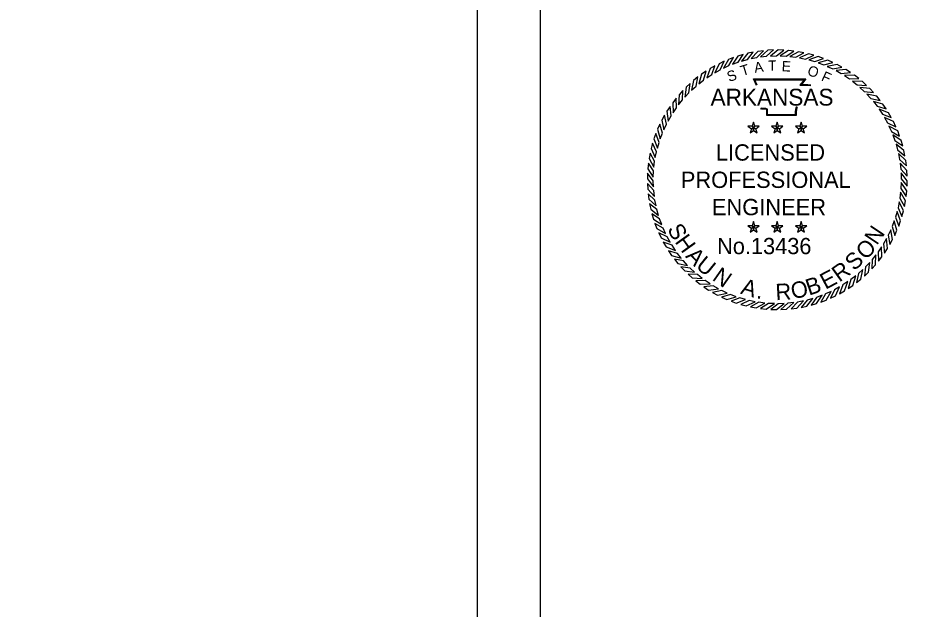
# Model space of a CAD drawing. Extents: x 759422 to 1448857, y 1662254 to 2059437.
# Drawn here: x 1448448.5 to 1448856.9, y 2058891.6 to 2059163.3 of the extents above; entities that cross this region are included whole.
import ezdxf

# ---------------------------------------------------------------- set-up
doc = ezdxf.new("R2010")
doc.units = 0
doc.layers.add('1', color=7, linetype='Continuous')
doc.layers.add('G-ANNO-SYMB', color=7, linetype='Continuous')

msp = doc.modelspace()

# ---------------------------------------------------------------- linework, layer by layer
at = {"layer": '1'}
msp.add_line((1448659.58, 2058365.37), (1448659.58, 2059407.69), dxfattribs=at)
msp.add_lwpolyline([(1448688.42, 2059436.53), (1446988.42, 2059436.53), (1446988.42, 2058336.53), (1448688.42, 2058336.53)], close=True, dxfattribs=at)
at = {"layer": 'G-ANNO-SYMB'}
for points in [[(1448781.61, 2059146.49), (1448779.15, 2059145.77), (1448776.6, 2059141.98), (1448779.2, 2059142.92)], [(1448786.18, 2059147.54), (1448783.67, 2059147.01), (1448780.82, 2059143.43), (1448783.5, 2059144.16)], [(1448790.82, 2059148.22), (1448788.27, 2059147.89), (1448785.15, 2059144.55), (1448787.87, 2059145.07)], [(1448795.49, 2059148.54), (1448792.93, 2059148.41), (1448789.56, 2059145.32), (1448792.31, 2059145.63)], [(1448800.17, 2059148.49), (1448797.61, 2059148.56), (1448794.01, 2059145.75), (1448796.78, 2059145.83)], [(1448804.84, 2059148.07), (1448802.29, 2059148.34), (1448798.48, 2059145.82), (1448801.24, 2059145.69)], [(1448809.46, 2059147.29), (1448806.94, 2059147.76), (1448802.94, 2059145.54), (1448805.69, 2059145.2)], [(1448814, 2059146.15), (1448811.52, 2059146.82), (1448807.36, 2059144.92), (1448810.08, 2059144.36)], [(1448818.44, 2059144.65), (1448816.02, 2059145.51), (1448811.73, 2059143.95), (1448814.39, 2059143.18)], [(1448768.6, 2059141.26), (1448766.38, 2059139.99), (1448764.78, 2059135.7), (1448767.09, 2059137.23)], [(1448772.8, 2059143.35), (1448770.48, 2059142.25), (1448768.55, 2059138.1), (1448770.98, 2059139.44)], [(1448777.14, 2059145.09), (1448774.75, 2059144.18), (1448772.5, 2059140.2), (1448775.02, 2059141.34)], [(1448822.75, 2059142.81), (1448820.41, 2059143.86), (1448816, 2059142.64), (1448818.59, 2059141.66)], [(1448826.9, 2059140.64), (1448824.65, 2059141.87), (1448820.16, 2059141), (1448822.67, 2059139.82)], [(1448764.58, 2059138.86), (1448762.46, 2059137.41), (1448761.2, 2059133.02), (1448763.39, 2059134.71)], [(1448830.87, 2059138.15), (1448828.72, 2059139.55), (1448824.18, 2059139.04), (1448826.58, 2059137.66)], [(1448757.17, 2059133.14), (1448755.3, 2059131.38), (1448754.75, 2059126.84), (1448756.64, 2059128.86)], [(1448760.76, 2059136.15), (1448758.76, 2059134.54), (1448757.85, 2059130.06), (1448759.9, 2059131.92)], [(1448834.63, 2059135.36), (1448832.6, 2059136.92), (1448828.03, 2059136.76), (1448830.32, 2059135.21)], [(1448838.16, 2059132.28), (1448836.25, 2059134), (1448831.69, 2059134.2), (1448833.85, 2059132.47)], [(1448753.82, 2059129.87), (1448752.1, 2059127.96), (1448751.9, 2059123.39), (1448753.63, 2059125.56)], [(1448841.43, 2059128.93), (1448839.67, 2059130.79), (1448835.13, 2059131.35), (1448837.15, 2059129.45)], [(1448750.74, 2059126.34), (1448749.17, 2059124.3), (1448749.33, 2059119.73), (1448750.89, 2059122.03)], [(1448844.44, 2059125.34), (1448842.83, 2059127.33), (1448838.35, 2059128.24), (1448840.21, 2059126.19)], [(1448847.15, 2059121.52), (1448845.7, 2059123.63), (1448841.31, 2059124.89), (1448843.01, 2059122.7)], [(1448747.95, 2059122.58), (1448746.54, 2059120.43), (1448747.06, 2059115.88), (1448748.43, 2059118.29)], [(1448849.56, 2059117.5), (1448848.28, 2059119.72), (1448843.99, 2059121.32), (1448845.52, 2059119.01)], [(1448745.46, 2059118.61), (1448744.23, 2059116.36), (1448745.1, 2059111.87), (1448746.28, 2059114.38)], [(1448851.64, 2059113.3), (1448850.54, 2059115.62), (1448846.39, 2059117.55), (1448847.73, 2059115.12)], [(1448743.28, 2059114.46), (1448742.24, 2059112.12), (1448743.46, 2059107.71), (1448744.44, 2059110.3)], [(1448786.28, 2059112.66), (1448785.67, 2059113.5), (1448783.69, 2059113.5), (1448785.29, 2059112.34)], [(1448786.28, 2059112.66), (1448785.29, 2059112.34), (1448784.68, 2059110.45), (1448786.28, 2059111.62)], [(1448786.28, 2059112.66), (1448786.9, 2059113.5), (1448786.28, 2059115.39), (1448785.67, 2059113.5)], [(1448786.28, 2059112.66), (1448787.28, 2059112.34), (1448788.88, 2059113.5), (1448786.9, 2059113.5)], [(1448786.28, 2059112.66), (1448786.28, 2059111.62), (1448787.89, 2059110.45), (1448787.28, 2059112.34)], [(1448797.19, 2059112.66), (1448796.58, 2059113.5), (1448794.6, 2059113.5), (1448796.2, 2059112.34)], [(1448797.19, 2059112.66), (1448796.2, 2059112.34), (1448795.59, 2059110.45), (1448797.19, 2059111.62)], [(1448797.19, 2059112.66), (1448797.81, 2059113.5), (1448797.19, 2059115.39), (1448796.58, 2059113.5)], [(1448797.19, 2059112.66), (1448798.18, 2059112.34), (1448799.79, 2059113.5), (1448797.81, 2059113.5)], [(1448797.19, 2059112.66), (1448797.19, 2059111.62), (1448798.8, 2059110.45), (1448798.18, 2059112.34)], [(1448808.1, 2059112.66), (1448807.49, 2059113.5), (1448805.51, 2059113.5), (1448807.11, 2059112.34)], [(1448808.1, 2059112.66), (1448807.11, 2059112.34), (1448806.5, 2059110.45), (1448808.1, 2059111.62)], [(1448808.1, 2059112.66), (1448808.72, 2059113.5), (1448808.1, 2059115.39), (1448807.49, 2059113.5)], [(1448808.1, 2059112.66), (1448809.09, 2059112.34), (1448810.7, 2059113.5), (1448808.72, 2059113.5)], [(1448808.1, 2059112.66), (1448808.1, 2059111.62), (1448809.71, 2059110.45), (1448809.09, 2059112.34)], [(1448853.38, 2059108.95), (1448852.47, 2059111.35), (1448848.49, 2059113.6), (1448849.63, 2059111.08)], [(1448741.45, 2059110.15), (1448740.58, 2059107.73), (1448742.15, 2059103.44), (1448742.92, 2059106.1)], [(1448854.78, 2059104.48), (1448854.06, 2059106.94), (1448850.27, 2059109.5), (1448851.21, 2059106.89)], [(1448739.95, 2059105.71), (1448739.28, 2059103.23), (1448741.18, 2059099.07), (1448741.74, 2059101.79)], [(1448855.83, 2059099.92), (1448855.3, 2059102.43), (1448851.72, 2059105.27), (1448852.45, 2059102.6)], [(1448738.81, 2059101.17), (1448738.34, 2059098.65), (1448740.55, 2059094.65), (1448740.9, 2059097.4)], [(1448856.51, 2059095.28), (1448856.18, 2059097.83), (1448852.84, 2059100.94), (1448853.36, 2059098.22)], [(1448738.03, 2059096.55), (1448737.75, 2059094), (1448740.28, 2059090.18), (1448740.41, 2059092.95)], [(1448856.83, 2059090.61), (1448856.7, 2059093.17), (1448853.61, 2059096.54), (1448853.92, 2059093.79)], [(1448737.61, 2059091.88), (1448737.54, 2059089.32), (1448740.35, 2059085.71), (1448740.26, 2059088.48)], [(1448856.78, 2059085.92), (1448856.85, 2059088.49), (1448854.04, 2059092.09), (1448854.12, 2059089.32)], [(1448737.56, 2059087.2), (1448737.69, 2059084.64), (1448740.78, 2059081.26), (1448740.47, 2059084.02)], [(1448856.36, 2059081.26), (1448856.64, 2059083.81), (1448854.11, 2059087.62), (1448853.98, 2059084.85)], [(1448737.88, 2059082.52), (1448738.21, 2059079.98), (1448741.55, 2059076.86), (1448741.03, 2059079.58)], [(1448855.58, 2059076.64), (1448856.05, 2059079.16), (1448853.84, 2059083.16), (1448853.49, 2059080.41)], [(1448738.56, 2059077.89), (1448739.09, 2059075.38), (1448742.67, 2059072.53), (1448741.93, 2059075.21)], [(1448854.44, 2059072.1), (1448855.11, 2059074.57), (1448853.21, 2059078.73), (1448852.65, 2059076.02)], [(1448739.6, 2059073.32), (1448740.33, 2059070.86), (1448744.12, 2059068.31), (1448743.18, 2059070.91)], [(1448852.94, 2059067.66), (1448853.8, 2059070.07), (1448852.24, 2059074.37), (1448851.47, 2059071.71)], [(1448741, 2059068.85), (1448741.92, 2059066.46), (1448745.9, 2059064.2), (1448744.76, 2059066.73)], [(1448786.28, 2059066.98), (1448785.67, 2059067.82), (1448783.69, 2059067.82), (1448785.29, 2059066.66)], [(1448786.28, 2059066.98), (1448786.9, 2059067.82), (1448786.28, 2059069.7), (1448785.67, 2059067.82)], [(1448786.28, 2059066.98), (1448787.28, 2059066.66), (1448788.88, 2059067.82), (1448786.9, 2059067.82)], [(1448797.19, 2059066.98), (1448796.58, 2059067.82), (1448794.6, 2059067.82), (1448796.2, 2059066.66)], [(1448797.19, 2059066.98), (1448797.81, 2059067.82), (1448797.19, 2059069.7), (1448796.58, 2059067.82)], [(1448797.19, 2059066.98), (1448798.18, 2059066.66), (1448799.79, 2059067.82), (1448797.81, 2059067.82)], [(1448808.1, 2059066.98), (1448807.49, 2059067.82), (1448805.51, 2059067.82), (1448807.11, 2059066.66)], [(1448808.1, 2059066.98), (1448808.72, 2059067.82), (1448808.1, 2059069.7), (1448807.49, 2059067.82)], [(1448808.1, 2059066.98), (1448809.09, 2059066.66), (1448810.7, 2059067.82), (1448808.72, 2059067.82)], [(1448851.1, 2059063.35), (1448852.15, 2059065.69), (1448850.93, 2059070.1), (1448849.95, 2059067.5)], [(1448742.75, 2059064.51), (1448743.85, 2059062.19), (1448747.99, 2059060.26), (1448746.66, 2059062.68)], [(1448786.28, 2059066.98), (1448785.29, 2059066.66), (1448784.68, 2059064.77), (1448786.28, 2059065.94)], [(1448786.28, 2059066.98), (1448786.28, 2059065.94), (1448787.89, 2059064.77), (1448787.28, 2059066.66)], [(1448797.19, 2059066.98), (1448796.2, 2059066.66), (1448795.59, 2059064.77), (1448797.19, 2059065.94)], [(1448797.19, 2059066.98), (1448797.19, 2059065.94), (1448798.8, 2059064.77), (1448798.18, 2059066.66)], [(1448808.1, 2059066.98), (1448807.11, 2059066.66), (1448806.5, 2059064.77), (1448808.1, 2059065.94)], [(1448808.1, 2059066.98), (1448808.1, 2059065.94), (1448809.71, 2059064.77), (1448809.09, 2059066.66)], [(1448848.93, 2059059.2), (1448850.16, 2059061.45), (1448849.29, 2059065.94), (1448848.11, 2059063.43)], [(1448744.83, 2059060.31), (1448746.11, 2059058.09), (1448750.39, 2059056.48), (1448748.87, 2059058.8)], [(1448846.44, 2059055.23), (1448847.84, 2059057.38), (1448847.33, 2059061.92), (1448845.95, 2059059.51)], [(1448747.24, 2059056.29), (1448748.69, 2059054.17), (1448753.08, 2059052.91), (1448751.38, 2059055.1)], [(1448843.65, 2059051.47), (1448845.21, 2059053.5), (1448845.06, 2059058.07), (1448843.5, 2059055.78)], [(1448749.95, 2059052.47), (1448751.56, 2059050.47), (1448756.04, 2059049.56), (1448754.18, 2059051.61)], [(1448840.57, 2059047.94), (1448842.29, 2059049.84), (1448842.49, 2059054.41), (1448840.76, 2059052.25)], [(1448752.95, 2059048.88), (1448754.72, 2059047.01), (1448759.25, 2059046.45), (1448757.23, 2059048.35)], [(1448833.63, 2059041.66), (1448835.62, 2059043.27), (1448836.54, 2059047.75), (1448834.49, 2059045.88)], [(1448837.22, 2059044.66), (1448839.09, 2059046.43), (1448839.64, 2059050.96), (1448837.75, 2059048.94)], [(1448756.23, 2059045.53), (1448758.13, 2059043.81), (1448762.7, 2059043.61), (1448760.54, 2059045.34)], [(1448829.81, 2059038.95), (1448831.92, 2059040.4), (1448833.19, 2059044.79), (1448831, 2059043.09)], [(1448759.76, 2059042.45), (1448761.79, 2059040.88), (1448766.36, 2059041.04), (1448764.07, 2059042.6)], [(1448763.52, 2059039.66), (1448765.67, 2059038.25), (1448770.21, 2059038.77), (1448767.8, 2059040.14)], [(1448821.59, 2059034.46), (1448823.91, 2059035.56), (1448825.84, 2059039.7), (1448823.41, 2059038.37)], [(1448825.79, 2059036.54), (1448828.01, 2059037.82), (1448829.61, 2059042.1), (1448827.3, 2059040.58)], [(1448767.49, 2059037.16), (1448769.74, 2059035.94), (1448774.23, 2059036.81), (1448771.72, 2059037.99)], [(1448771.64, 2059034.99), (1448773.98, 2059033.94), (1448778.39, 2059035.17), (1448775.79, 2059036.15)], [(1448812.77, 2059031.31), (1448815.24, 2059032.04), (1448817.79, 2059035.83), (1448815.18, 2059034.89)], [(1448817.24, 2059032.71), (1448819.64, 2059033.63), (1448821.89, 2059037.61), (1448819.37, 2059036.47)], [(1448775.95, 2059033.15), (1448778.36, 2059032.29), (1448782.66, 2059033.86), (1448780, 2059034.63)], [(1448780.39, 2059031.66), (1448782.86, 2059030.99), (1448787.03, 2059032.89), (1448784.31, 2059033.45)], [(1448784.93, 2059030.52), (1448787.45, 2059030.04), (1448791.45, 2059032.26), (1448788.7, 2059032.61)], [(1448789.55, 2059029.74), (1448792.1, 2059029.46), (1448795.91, 2059031.99), (1448793.14, 2059032.12)], [(1448794.22, 2059029.32), (1448796.78, 2059029.25), (1448800.38, 2059032.06), (1448797.61, 2059031.97)], [(1448798.9, 2059029.27), (1448801.46, 2059029.4), (1448804.83, 2059032.49), (1448802.08, 2059032.18)], [(1448803.57, 2059029.59), (1448806.12, 2059029.91), (1448809.24, 2059033.26), (1448806.51, 2059032.74)], [(1448808.21, 2059030.27), (1448810.72, 2059030.8), (1448813.56, 2059034.38), (1448810.89, 2059033.64)]]:
    msp.add_lwpolyline(points, close=True, dxfattribs=at)
for points in [[(1448787.64, 2059132.2), (1448786.25, 2059135.21), (1448810.31, 2059135.23), (1448808.3, 2059132.7), (1448809.93, 2059132.72), (1448811.3, 2059132.74), (1448812.66, 2059132.59)], [(1448787.98, 2059132.36), (1448786.84, 2059134.83), (1448809.52, 2059134.85), (1448807.5, 2059132.31), (1448809.94, 2059132.34), (1448811.28, 2059132.36), (1448812.62, 2059132.21)], [(1448806.52, 2059122.12), (1448806.11, 2059121.78), (1448805.97, 2059121.29), (1448805.83, 2059120.04), (1448805.83, 2059118.37), (1448792.4, 2059118.37), (1448792.4, 2059120.62), (1448792.4, 2059121.12), (1448791.86, 2059121.29), (1448789.95, 2059121.29), (1448789.61, 2059121.8)], [(1448806.28, 2059122.41), (1448805.77, 2059122), (1448805.6, 2059121.36), (1448805.45, 2059120.06), (1448805.45, 2059118.76), (1448792.78, 2059118.76), (1448792.78, 2059120.62), (1448792.78, 2059121.4), (1448791.91, 2059121.67), (1448790.15, 2059121.67), (1448789.93, 2059122.01)]]:
    msp.add_lwpolyline(points, dxfattribs=at)

# ---------------------------------------------------------------- texts
for s, height, rotation, p in [('T', 4.75, 16.9015, (1448781.14, 2059136.49)), ('A', 4.75, 8.6788, (1448786.9, 2059138)), ('T', 4.75, 1.4789, (1448793.03, 2059138.94)), ('E', 4.75, 356.672, (1448799.11, 2059138.8)), ('O', 4.75, 341.2218, (1448810.63, 2059137.17)), ('S', 4.75, 19.7726, (1448775.1, 2059133.78)), ('F', 4.75, 335.3628, (1448817.03, 2059134.67)), ('ARKANSAS', 7.747, 360, (1448766.57, 2059122.98)), ('LICENSED', 7.5, 360, (1448768.98, 2059097.7)), ('PROFESSIONAL', 7.5, 360, (1448752.91, 2059085.15)), ('ENGINEER', 7.5, 360, (1448767.19, 2059072.61)), ('S', 7.5, 298.1636, (1448746.51, 2059066.31)), ('N', 7.5, 56.1007, (1448842.93, 2059058.47)), ('H', 7.5, 305.619, (1448749.93, 2059060.43)), ('No.13436', 7.47, 360, (1448769.56, 2059054.73)), ('O', 7.5, 44.7757, (1448837.73, 2059051.72)), ('A', 7.5, 313.4472, (1448754.7, 2059053.58)), ('S', 7.5, 43.4878, (1448832.57, 2059046.74)), ('U', 7.5, 320.9026, (1448759.37, 2059048.69)), ('N', 7.5, 324.9326, (1448766.93, 2059043.1)), ('E', 7.5, 27.8315, (1448819.34, 2059038.32)), ('R', 7.5, 35.6597, (1448825.68, 2059041.64)), ('B', 7.5, 18.885, (1448811.76, 2059035.61)), ('A', 7.5, 343.0991, (1448780, 2059036.67)), ('R', 7.5, 3.2287, (1448796.57, 2059033.54)), ('O', 7.5, 11.4296, (1448804.24, 2059034.02)), ('.', 7.5, 351.3, (1448787.37, 2059034.49))]:
    msp.add_text(s, height=height, rotation=rotation, dxfattribs=at).set_placement(p)

doc.saveas('drawing.dxf')
